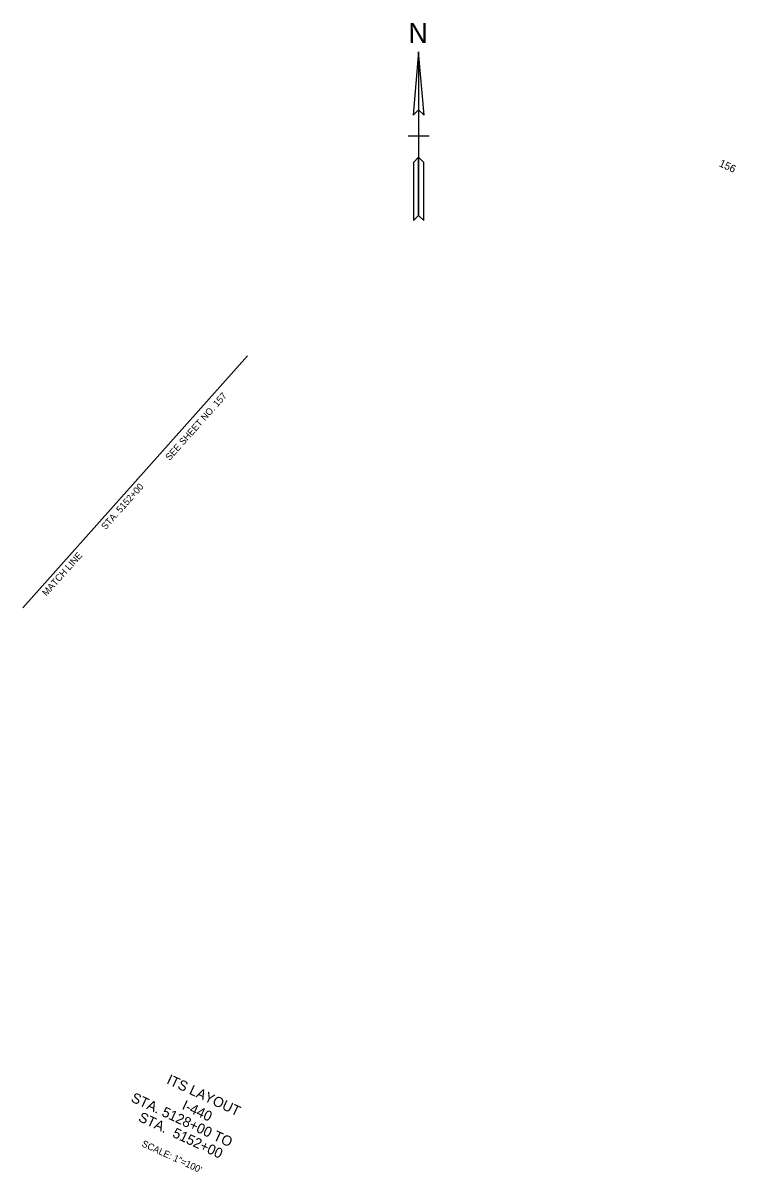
# Model space of a CAD drawing. Extents: x -200 to 1732094, y -325 to 653206.
# Drawn here: x 1730826 to 1732094, y 650877 to 652921 of the extents above; entities that cross this region are included whole.
import ezdxf

# ---------------------------------------------------------------- set-up
doc = ezdxf.new("R2010")
doc.units = 0
for name, color, linetype in [('DESIGN - CENTERLINE - Proposed Text', 7, 'Continuous'), ('DESIGN - SCRATCH - User 1', 7, 'Continuous'), ('DESIGN - SHEET - Corner Text', 7, 'Continuous'), ('ITS - CONST TEXT', 7, 'Continuous'), ('ITS - EXISITING WEATHER STATION', 7, 'Continuous'), ('ITS - EXISTING COMM CABLE', 7, 'Continuous'), ('ITS - EXISTING HAR', 7, 'Continuous')]:
    doc.layers.add(name, color=color, linetype=linetype)

msp = doc.modelspace()

# ---------------------------------------------------------------- linework, layer by layer
at = {"layer": 'DESIGN - CENTERLINE - Proposed Text'}
for p, q in [((1731529.3, 652719.7), (1731510.4, 652719.7)), ((1731548.2, 652719.7), (1731529.3, 652719.7))]:
    msp.add_line(p, q, dxfattribs=at)
msp.add_lwpolyline([(1731529.3, 652869.7), (1731519.5, 652757.1), (1731529.3, 652766.9), (1731539.1, 652757.1), (1731529.3, 652869.7), (1731529.3, 652578.8), (1731538.4, 652569.7), (1731538.4, 652673.2), (1731529.3, 652682.3), (1731520.2, 652673.2), (1731520.2, 652569.7), (1731529.3, 652578.8)], dxfattribs=at)
for points in [[(1731529.3, 652766.9), (1731539.1, 652757.1), (1731529.3, 652869.7)], [(1731520.2, 652569.7), (1731529.3, 652578.8), (1731529.3, 652682.3), (1731520.2, 652673.2)]]:
    msp.add_lwpolyline(points, close=True, dxfattribs=at)
at = {"layer": 'DESIGN - SCRATCH - User 1'}
for p, q in [((1731144, 650967.5), (1731144, 650967.5)), ((1731144, 650967.5), (1731144, 650967.5)), ((1731140, 650951.3), (1731140, 650951.3))]:
    msp.add_line(p, q, dxfattribs=at)
at = {"layer": 'ITS - EXISITING WEATHER STATION'}
msp.add_line((1731143.9, 650967.6), (1731143.9, 650967.6), dxfattribs=at)
msp.add_line((1731143.9, 650967.6), (1731143.9, 650967.6), dxfattribs=at)
at = {"layer": 'ITS - EXISTING COMM CABLE'}
msp.add_line((1730825.5, 651880.8), (1731224.6, 652328.8), dxfattribs=at)

# ---------------------------------------------------------------- texts
at = {"layer": 'DESIGN - CENTERLINE - Proposed Text'}
msp.add_text('N', height=35.4, dxfattribs=at).set_placement((1731511.2, 652885.8))
at = {"layer": 'DESIGN - SHEET - Corner Text'}
msp.add_text('156', height=13.5, rotation=335.0924, dxfattribs=at).set_placement((1732062.4, 652666.9))
at = {"layer": 'ITS - CONST TEXT'}
msp.add_text('SCALE: 1"=100\'', height=12, rotation=335.0925, dxfattribs=at).set_placement((1731035.6, 650923))
at = {"layer": 'ITS - EXISTING COMM CABLE'}
for s, p in [('SEE SHEET NO. 157 ', (1731086.5, 652141.9)), ('STA. 5152+00', (1730972.4, 652018.6)), ('MATCH LINE', (1730867.3, 651900.6))]:
    msp.add_text(s, height=12, rotation=48.3049, dxfattribs=at).set_placement(p)
at = {"layer": 'ITS - EXISTING HAR'}
for s, p in [('ITS LAYOUT', (1731079.7, 651034.8)), ('STA. 5128+00 TO', (1731016.3, 651002.6)), ('I-440', (1731106.9, 650989.2)), ('STA.  5152+00', (1731029.3, 650968))]:
    msp.add_text(s, height=18, rotation=335.0925, dxfattribs=at).set_placement(p)

doc.saveas('drawing.dxf')
